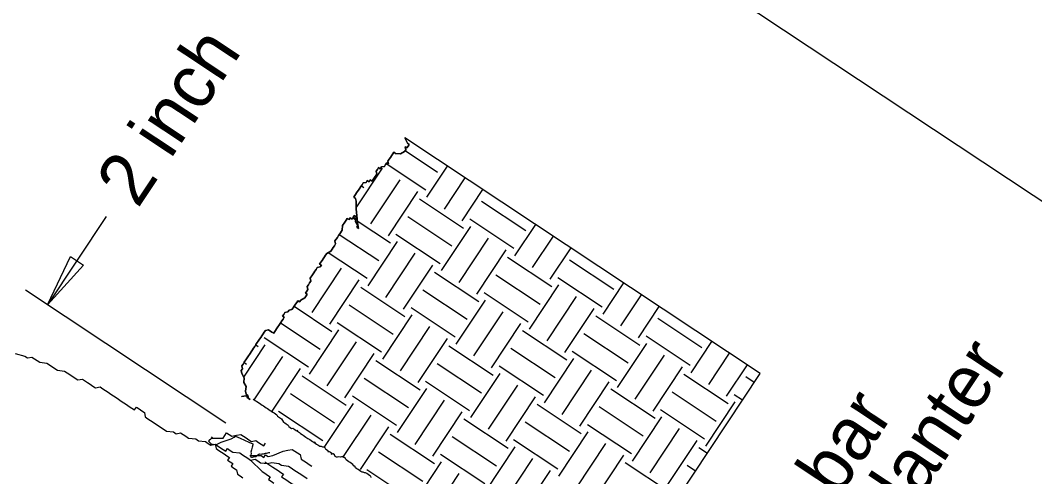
# Model space of a CAD drawing. Extents: x 561231 to 564240, y 590260 to 602519.
# Drawn here: x 563580.5 to 563651.6, y 590919.7 to 590951.7 of the extents above; entities that cross this region are included whole.
import ezdxf

# ---------------------------------------------------------------- set-up
doc = ezdxf.new("R2010")
doc.units = 0
doc.layers.add('Old_Level_1', color=7, linetype='Continuous')

msp = doc.modelspace()

# ---------------------------------------------------------------- linework, layer by layer
at = {"layer": 'Old_Level_1'}
for p, q in [((563974.316, 590725.26), (563449.318, 591073.509)), ((563632.39, 590926.921), (563607.472, 590943.449)), ((563607.495, 590942.538), (563609.769, 590941.03)), ((563606.175, 590941.628), (563608.947, 590939.79)), ((563604.064, 590938.534), (563605.914, 590941.322)), ((563609.015, 590939.266), (563610.47, 590941.461)), ((563605.098, 590937.399), (563607.154, 590940.5)), ((563610.255, 590938.444), (563611.71, 590940.638)), ((563604.427, 590940.077), (563604.597, 590939.963)), ((563606.338, 590936.577), (563608.395, 590939.677)), ((563611.495, 590937.621), (563612.95, 590939.815)), ((563608.499, 590939.161), (563611.599, 590937.105)), ((563612.848, 590938.988), (563615.949, 590936.931)), ((563586.548, 590937.919), (563582.435, 590931.718)), ((563603.831, 590937.825), (563604.039, 590937.688)), ((563604.139, 590937.622), (563606.479, 590936.069)), ((563607.676, 590937.921), (563610.777, 590935.865)), ((563612.025, 590937.747), (563615.126, 590935.691)), ((563615.194, 590935.167), (563616.65, 590937.362)), ((563602.884, 590936.668), (563605.656, 590934.829)), ((563606.854, 590936.681), (563609.954, 590934.625)), ((563610.036, 590934.124), (563612.093, 590937.224)), ((563616.434, 590934.344), (563617.889, 590936.539)), ((563604.902, 590933.065), (563606.958, 590936.165)), ((563611.277, 590933.301), (563613.333, 590936.401)), ((563602.108, 590935.397), (563604.834, 590933.589)), ((563606.142, 590932.242), (563608.198, 590935.343)), ((563612.517, 590932.478), (563614.573, 590935.579)), ((563617.674, 590933.522), (563619.129, 590935.717)), ((563607.382, 590931.42), (563609.439, 590934.52)), ((563614.678, 590935.063), (563617.779, 590933.006)), ((563619.027, 590934.889), (563622.128, 590932.833)), ((563600.984, 590931.199), (563603.041, 590934.299)), ((563609.558, 590934.027), (563612.658, 590931.971)), ((563613.855, 590933.822), (563616.956, 590931.766)), ((563602.225, 590930.376), (563604.281, 590933.477)), ((563616.216, 590930.024), (563618.272, 590933.125)), ((563618.205, 590933.649), (563621.305, 590931.592)), ((563621.373, 590931.068), (563622.828, 590933.263)), ((563594.917, 590923.438), (563580.885, 590932.746)), ((563604.386, 590932.961), (563607.486, 590930.904)), ((563608.735, 590932.787), (563611.835, 590930.731)), ((563613.033, 590932.583), (563616.133, 590930.526)), ((563617.456, 590929.202), (563619.512, 590932.303)), ((563622.613, 590930.246), (563624.069, 590932.44)), ((563599.718, 590931.625), (563602.366, 590929.869)), ((563603.563, 590931.721), (563606.664, 590929.664)), ((563611.081, 590928.966), (563613.137, 590932.067)), ((563623.853, 590929.423), (563625.309, 590931.618)), ((563605.923, 590927.922), (563607.98, 590931.023)), ((563607.912, 590931.547), (563611.013, 590929.49)), ((563612.321, 590928.144), (563614.377, 590931.244)), ((563618.696, 590928.379), (563620.752, 590931.48)), ((563620.857, 590930.964), (563623.957, 590928.907)), ((563598.771, 590930.467), (563601.543, 590928.628)), ((563602.741, 590930.48), (563605.841, 590928.424)), ((563607.164, 590927.1), (563609.22, 590930.2)), ((563613.561, 590927.321), (563615.618, 590930.422)), ((563625.206, 590930.79), (563628.307, 590928.734)), ((563597.62, 590929.445), (563600.721, 590927.388)), ((563600.788, 590926.864), (563602.845, 590929.965)), ((563615.737, 590929.928), (563618.837, 590927.872)), ((563620.035, 590929.724), (563623.135, 590927.667)), ((563624.384, 590929.55), (563627.484, 590927.494)), ((563596.192, 590926.666), (563597.688, 590928.921)), ((563597.024, 590928.915), (563597.194, 590928.802)), ((563602.028, 590926.042), (563604.085, 590929.142)), ((563608.404, 590926.277), (563610.46, 590929.378)), ((563610.565, 590928.862), (563613.665, 590926.805)), ((563622.395, 590925.926), (563624.452, 590929.026)), ((563627.552, 590926.97), (563629.007, 590929.164)), ((563596.914, 590925.062), (563598.928, 590928.098)), ((563603.268, 590925.219), (563605.325, 590928.319)), ((563614.914, 590928.688), (563618.015, 590926.632)), ((563619.212, 590928.484), (563622.312, 590926.427)), ((563623.635, 590925.103), (563625.692, 590928.203)), ((563628.792, 590926.147), (563630.247, 590928.341)), ((563596.201, 590927.675), (563596.371, 590927.562)), ((563605.445, 590927.826), (563608.545, 590925.77)), ((563609.742, 590927.622), (563612.842, 590925.565)), ((563614.092, 590927.448), (563617.192, 590925.392)), ((563617.26, 590924.868), (563619.316, 590927.968)), ((563624.875, 590924.281), (563626.932, 590927.381)), ((563630.032, 590925.324), (563631.488, 590927.519)), ((563598.13, 590924.202), (563600.168, 590927.275)), ((563600.273, 590926.76), (563603.373, 590924.703)), ((563604.622, 590926.586), (563607.722, 590924.53)), ((563607.942, 590890.064), (563632.39, 590926.921)), ((563612.102, 590923.824), (563614.159, 590926.924)), ((563618.5, 590924.045), (563620.556, 590927.145)), ((563627.036, 590926.865), (563630.136, 590924.809)), ((563631.385, 590926.692), (563631.978, 590926.299)), ((563608.92, 590926.382), (563612.02, 590924.325)), ((563613.343, 590923.001), (563615.399, 590926.101)), ((563619.74, 590923.222), (563621.797, 590926.323)), ((563599.45, 590925.52), (563602.55, 590923.463)), ((563603.799, 590925.346), (563606.9, 590923.289)), ((563606.967, 590922.766), (563609.024, 590925.866)), ((563614.583, 590922.179), (563616.639, 590925.279)), ((563621.916, 590925.83), (563625.016, 590923.773)), ((563626.214, 590925.625), (563629.314, 590923.569)), ((563630.563, 590925.451), (563631.155, 590925.059)), ((563601.81, 590921.722), (563603.867, 590924.822)), ((563608.207, 590921.943), (563610.264, 590925.044)), ((563616.744, 590924.763), (563619.844, 590922.707)), ((563621.093, 590924.59), (563624.194, 590922.533)), ((563628.574, 590921.827), (563630.631, 590924.927)), ((563598.627, 590924.28), (563601.727, 590922.223)), ((563603.128, 590921.016), (563605.107, 590923.999)), ((563609.447, 590921.12), (563611.504, 590924.221)), ((563623.438, 590920.769), (563625.495, 590923.869)), ((563625.391, 590924.385), (563628.491, 590922.328)), ((563604.368, 590920.194), (563606.347, 590923.177)), ((563611.623, 590923.728), (563614.724, 590921.671)), ((563615.921, 590923.523), (563619.021, 590921.467)), ((563620.271, 590923.349), (563623.371, 590921.293)), ((563624.679, 590919.946), (563626.735, 590923.047)), ((563599.952, 590922.912), (563599.972, 590922.942)), ((563606.452, 590922.661), (563609.552, 590920.605)), ((563610.801, 590922.487), (563613.901, 590920.431)), ((563618.281, 590919.725), (563620.338, 590922.825)), ((563601.168, 590922.052), (563601.212, 590922.119)), ((563613.146, 590918.667), (563615.203, 590921.767)), ((563615.099, 590922.283), (563618.199, 590920.226)), ((563619.522, 590918.903), (563621.578, 590922.003)), ((563625.919, 590919.124), (563627.975, 590922.224)), ((563628.095, 590921.731), (563628.687, 590921.338)), ((563605.629, 590921.421), (563608.729, 590919.365)), ((563609.978, 590921.247), (563613.079, 590919.191)), ((563614.386, 590917.844), (563616.443, 590920.945)), ((563620.762, 590918.08), (563622.818, 590921.18)), ((563604.806, 590920.181), (563607.907, 590918.124)), ((563607.99, 590917.623), (563610.046, 590920.723)), ((563622.923, 590920.664), (563626.023, 590918.608)), ((563627.272, 590920.491), (563627.864, 590920.098)), ((563609.23, 590916.801), (563611.286, 590919.901)), ((563615.627, 590917.022), (563617.683, 590920.122))]:
    msp.add_line(p, q, dxfattribs=at)
for points in [[(563603.115, 590937.286), (563603.28, 590937.535), (563603.362, 590937.659), (563603.445, 590937.784), (563603.57, 590937.701), (563603.652, 590937.826), (563603.776, 590937.743), (563603.652, 590937.826), (563603.776, 590937.743), (563603.859, 590937.868), (563603.984, 590937.785), (563603.859, 590937.868), (563603.942, 590937.992), (563604.067, 590937.909), (563604.026, 590937.578), (563604.192, 590937.288), (563604.11, 590937.164), (563604.234, 590937.081), (563604.15, 590937.495), (563604.065, 590938.448), (563604.064, 590938.988), (563604.022, 590939.195), (563603.897, 590939.277), (563603.979, 590939.402), (563604.144, 590939.651), (563604.227, 590939.775), (563604.31, 590939.9), (563604.392, 590940.024), (563604.475, 590940.149), (563604.558, 590940.273), (563604.765, 590940.315), (563604.847, 590940.439), (563604.972, 590940.357), (563605.055, 590940.482), (563605.18, 590940.399), (563605.262, 590940.523), (563605.345, 590940.648), (563605.51, 590940.897), (563605.468, 590941.104), (563605.55, 590941.228), (563605.633, 590941.353), (563605.757, 590941.27), (563605.84, 590941.395), (563606.047, 590941.436), (563606.13, 590941.561), (563606.213, 590941.686), (563606.337, 590941.603), (563606.295, 590941.81), (563606.378, 590941.935), (563606.46, 590942.059), (563606.543, 590942.184), (563606.625, 590942.308), (563606.708, 590942.433), (563606.833, 590942.35), (563607.164, 590942.31), (563607.454, 590942.476), (563607.537, 590942.6), (563607.494, 590942.808), (563607.619, 590942.725), (563607.702, 590942.85), (563607.785, 590942.974), (563607.659, 590943.057), (563607.472, 590943.449), (563607.472, 590943.449)], [(563607.472, 590943.449), (563607.472, 590943.449), (563607.659, 590943.057), (563607.785, 590942.974), (563607.702, 590942.85), (563607.619, 590942.725), (563607.494, 590942.808), (563607.537, 590942.6), (563607.454, 590942.476), (563607.164, 590942.31), (563606.833, 590942.35), (563606.708, 590942.433), (563606.625, 590942.308), (563606.543, 590942.184), (563606.46, 590942.059), (563606.378, 590941.935), (563606.295, 590941.81), (563606.337, 590941.603), (563606.213, 590941.686), (563606.13, 590941.561), (563606.047, 590941.436), (563605.84, 590941.395), (563605.757, 590941.27), (563605.633, 590941.353), (563605.55, 590941.228), (563605.468, 590941.104), (563605.51, 590940.897), (563605.345, 590940.648), (563605.262, 590940.523), (563605.18, 590940.399), (563605.055, 590940.482), (563604.972, 590940.357), (563604.847, 590940.439), (563604.765, 590940.315), (563604.558, 590940.273), (563604.475, 590940.149), (563604.392, 590940.024), (563604.31, 590939.9), (563604.227, 590939.775), (563604.144, 590939.651), (563603.979, 590939.402), (563603.897, 590939.277), (563604.022, 590939.195), (563604.064, 590938.988), (563604.065, 590938.448), (563604.15, 590937.495), (563604.234, 590937.081), (563604.11, 590937.164), (563604.192, 590937.288), (563604.026, 590937.578), (563604.067, 590937.909), (563603.942, 590937.992), (563603.859, 590937.868), (563603.984, 590937.785), (563603.859, 590937.868), (563603.776, 590937.743), (563603.652, 590937.826), (563603.776, 590937.743), (563603.652, 590937.826), (563603.57, 590937.701), (563603.445, 590937.784), (563603.362, 590937.659), (563603.28, 590937.535), (563603.115, 590937.286)], [(563596.018, 590925.285), (563596.056, 590925.293), (563596.47, 590925.376), (563596.388, 590925.252), (563596.512, 590925.169), (563596.637, 590925.087), (563596.512, 590925.169), (563596.47, 590925.376), (563596.346, 590925.459), (563596.303, 590925.666), (563596.344, 590925.998), (563596.178, 590926.288), (563596.219, 590926.619), (563596.051, 590926.909), (563596.01, 590927.116), (563596.093, 590927.241), (563596.05, 590927.448), (563596.133, 590927.573), (563596.215, 590927.697), (563596.381, 590927.946), (563596.463, 590928.071), (563596.629, 590928.32), (563596.711, 590928.444), (563596.793, 590928.569), (563596.876, 590928.693), (563596.959, 590928.818), (563597.041, 590928.942), (563597.289, 590929.316), (563597.371, 590929.44), (563597.454, 590929.565), (563597.537, 590929.69), (563597.62, 590929.814), (563597.702, 590929.938), (563597.909, 590929.98), (563598.159, 590929.814), (563598.283, 590929.732), (563598.366, 590929.856), (563598.531, 590930.106), (563598.696, 590930.355), (563598.779, 590930.479), (563598.862, 590930.604), (563598.944, 590930.728), (563599.027, 590930.853), (563598.902, 590930.936), (563598.985, 590931.06), (563599.068, 590931.185), (563599.275, 590931.227), (563599.357, 590931.351), (563599.564, 590931.393), (563599.647, 590931.517), (563599.729, 590931.642), (563599.812, 590931.767), (563599.894, 590931.891), (563599.977, 590932.016), (563600.102, 590931.932), (563600.185, 590932.057), (563600.474, 590932.224), (563600.556, 590932.348), (563600.639, 590932.472), (563600.515, 590932.555), (563600.598, 590932.68), (563600.68, 590932.804), (563600.638, 590933.012), (563600.721, 590933.136), (563600.803, 590933.26), (563600.886, 590933.385), (563600.844, 590933.592), (563601.009, 590933.841), (563601.092, 590933.966), (563601.174, 590934.09), (563601.257, 590934.215), (563601.339, 590934.339), (563601.546, 590934.381), (563601.629, 590934.506), (563601.504, 590934.588), (563601.588, 590934.713), (563601.67, 590934.837), (563601.752, 590934.962), (563601.835, 590935.086), (563601.918, 590935.211), (563602, 590935.336), (563602.29, 590935.502), (563602.372, 590935.626), (563602.455, 590935.751), (563602.538, 590935.876), (563602.62, 590936), (563602.578, 590936.207), (563602.661, 590936.332), (563602.744, 590936.457), (563602.826, 590936.58), (563602.909, 590936.705), (563603.074, 590936.954), (563603.115, 590937.286)], [(563603.115, 590937.286), (563603.074, 590936.954), (563602.909, 590936.705), (563602.826, 590936.58), (563602.744, 590936.457), (563602.661, 590936.332), (563602.578, 590936.207), (563602.62, 590936), (563602.538, 590935.876), (563602.455, 590935.751), (563602.372, 590935.626), (563602.29, 590935.502), (563602, 590935.336), (563601.918, 590935.211), (563601.835, 590935.086), (563601.752, 590934.962), (563601.67, 590934.837), (563601.588, 590934.713), (563601.504, 590934.588), (563601.629, 590934.506), (563601.546, 590934.381), (563601.339, 590934.339), (563601.257, 590934.215), (563601.174, 590934.09), (563601.092, 590933.966), (563601.009, 590933.841), (563600.844, 590933.592), (563600.886, 590933.385), (563600.803, 590933.26), (563600.721, 590933.136), (563600.638, 590933.012), (563600.68, 590932.804), (563600.598, 590932.68), (563600.515, 590932.555), (563600.639, 590932.472), (563600.556, 590932.348), (563600.474, 590932.224), (563600.185, 590932.057), (563600.102, 590931.932), (563599.977, 590932.016), (563599.894, 590931.891), (563599.812, 590931.767), (563599.729, 590931.642), (563599.647, 590931.517), (563599.564, 590931.393), (563599.357, 590931.351), (563599.275, 590931.227), (563599.068, 590931.185), (563598.985, 590931.06), (563598.902, 590930.936), (563599.027, 590930.853), (563598.944, 590930.728), (563598.862, 590930.604), (563598.779, 590930.479), (563598.696, 590930.355), (563598.531, 590930.106), (563598.366, 590929.856), (563598.283, 590929.732), (563598.159, 590929.814), (563597.909, 590929.98), (563597.702, 590929.938), (563597.62, 590929.814), (563597.537, 590929.69), (563597.454, 590929.565), (563597.371, 590929.44), (563597.289, 590929.316), (563597.041, 590928.942), (563596.959, 590928.818), (563596.876, 590928.693), (563596.793, 590928.569), (563596.711, 590928.444), (563596.629, 590928.32), (563596.463, 590928.071), (563596.381, 590927.946), (563596.215, 590927.697), (563596.133, 590927.573), (563596.05, 590927.448), (563596.093, 590927.241), (563596.01, 590927.116), (563596.051, 590926.909), (563596.219, 590926.619), (563596.178, 590926.288), (563596.344, 590925.998), (563596.303, 590925.666), (563596.346, 590925.459), (563596.47, 590925.376), (563596.512, 590925.169), (563596.637, 590925.087), (563596.512, 590925.169), (563596.388, 590925.252), (563596.47, 590925.376), (563596.056, 590925.293), (563596.018, 590925.285)], [(563580.149, 590928.314), (563580.832, 590928.13), (563581.018, 590928.006), (563581.327, 590928.068), (563581.7, 590927.821), (563581.887, 590927.697), (563582.383, 590927.636), (563582.569, 590927.513), (563582.942, 590927.266), (563583.129, 590927.141), (563583.624, 590927.081), (563583.998, 590926.834), (563584.37, 590926.586), (563584.557, 590926.463), (563584.867, 590926.525), (563585.239, 590926.279), (563585.426, 590926.155), (563585.612, 590926.031), (563585.799, 590925.907), (563586.108, 590925.97), (563586.295, 590925.846), (563586.481, 590925.723), (563586.668, 590925.599), (563586.854, 590925.475), (563587.04, 590925.352), (563587.227, 590925.228), (563587.413, 590925.105), (563587.6, 590924.981), (563587.786, 590924.857), (563587.972, 590924.734), (563588.158, 590924.61), (563588.345, 590924.487), (563588.531, 590924.363), (563588.655, 590924.549), (563588.841, 590924.426), (563589.027, 590924.302), (563589.214, 590924.178), (563589.276, 590923.868), (563589.463, 590923.744), (563589.649, 590923.621), (563589.835, 590923.498), (563590.208, 590923.25), (563590.395, 590923.127), (563590.768, 590922.879), (563591.264, 590922.819), (563591.451, 590922.695), (563591.76, 590922.757), (563592.133, 590922.51), (563592.319, 590922.387), (563592.816, 590922.325), (563593.002, 590922.202), (563593.499, 590922.141), (563593.684, 590922.017), (563593.871, 590921.894), (563594.181, 590921.956), (563594.554, 590921.709), (563594.74, 590921.585), (563594.926, 590921.462), (563595.049, 590921.648), (563595.236, 590921.524), (563595.423, 590921.401), (563595.919, 590921.34), (563596.105, 590921.216), (563596.292, 590921.092), (563596.478, 590920.969), (563596.665, 590920.845), (563596.974, 590920.908), (563597.161, 590920.784), (563597.347, 590920.661), (563597.844, 590920.599), (563598.153, 590920.662), (563598.65, 590920.601), (563598.836, 590920.478), (563599.332, 590920.416), (563599.519, 590920.293), (563599.705, 590920.169), (563599.892, 590920.045), (563600.078, 590919.922), (563600.264, 590919.798), (563600.637, 590919.551)], [(563596.853, 590925.111), (563597.284, 590924.825), (563597.378, 590924.763), (563597.471, 590924.702), (563597.564, 590924.64), (563597.657, 590924.578), (563597.75, 590924.516), (563597.844, 590924.455), (563597.937, 590924.393), (563598.031, 590924.331), (563598.123, 590924.269), (563598.216, 590924.207), (563598.309, 590924.145), (563598.403, 590924.084), (563598.496, 590924.022), (563598.558, 590923.914), (563598.698, 590923.821), (563598.838, 590923.728), (563598.9, 590923.619), (563598.962, 590923.511), (563599.055, 590923.449), (563599.148, 590923.388), (563599.288, 590923.295), (563599.351, 590923.187), (563599.444, 590923.124), (563599.537, 590923.062), (563599.615, 590923.078), (563599.754, 590922.985), (563599.847, 590922.924), (563599.941, 590922.862), (563600.081, 590922.769), (563600.173, 590922.707), (563600.267, 590922.645), (563600.36, 590922.584), (563600.453, 590922.522), (563600.547, 590922.46), (563600.686, 590922.367), (563600.825, 590922.275), (563600.919, 590922.213), (563601.012, 590922.151), (563601.106, 590922.089), (563601.198, 590922.027), (563601.292, 590921.965), (563601.385, 590921.904), (563601.525, 590921.811), (563601.602, 590921.827), (563601.695, 590921.765), (563601.773, 590921.781), (563601.867, 590921.719), (563601.882, 590921.642), (563601.975, 590921.579), (563602.069, 590921.518), (563602.084, 590921.44), (563602.162, 590921.456), (563602.255, 590921.394), (563602.348, 590921.332), (563602.363, 590921.255), (563602.363, 590921.255), (563602.348, 590921.332)], [(563593.931, 590922.39), (563593.972, 590922.462), (563593.91, 590922.369), (563593.849, 590922.276), (563593.772, 590922.26), (563593.71, 590922.167), (563593.71, 590922.167), (563593.865, 590921.997), (563593.959, 590921.935), (563594.036, 590921.951), (563594.16, 590921.936), (563594.315, 590921.967), (563594.609, 590922.107), (563594.872, 590922.201), (563595.291, 590922.325), (563595.507, 590922.45), (563595.616, 590922.512), (563595.927, 590922.373), (563596.237, 590922.234), (563596.547, 590922.095), (563596.811, 590921.988), (563596.826, 590921.91), (563596.781, 590921.739), (563596.735, 590921.569), (563596.688, 590921.398), (563596.705, 590921.32), (563596.689, 590921.196), (563596.627, 590921.103), (563596.72, 590921.042), (563596.798, 590921.057), (563596.875, 590921.073), (563597.03, 590921.104), (563597.17, 590921.213), (563597.278, 590921.276), (563597.403, 590921.26), (563597.48, 590921.276), (563597.557, 590921.292), (563597.635, 590921.307), (563597.712, 590921.323), (563597.789, 590921.338), (563597.867, 590921.354), (563597.944, 590921.369), (563598.022, 590921.385)], [(563593.931, 590922.39), (563594.738, 590922.391), (563594.862, 590922.578), (563594.985, 590922.764), (563595.171, 590922.64), (563595.358, 590922.516), (563595.668, 590922.579), (563595.977, 590922.642), (563596.164, 590922.518), (563596.35, 590922.395), (563596.537, 590922.271), (563596.723, 590922.147), (563597.033, 590922.21), (563597.22, 590922.086), (563597.406, 590921.963), (563597.592, 590921.84), (563597.716, 590922.026)], [(563594.181, 590921.956), (563594.244, 590921.646), (563594.43, 590921.522), (563594.617, 590921.399), (563594.803, 590921.276), (563594.989, 590921.152), (563595.176, 590921.028), (563595.052, 590920.842), (563595.238, 590920.719), (563595.425, 590920.595), (563595.301, 590920.408), (563595.487, 590920.285), (563595.674, 590920.161), (563595.737, 590919.851), (563595.924, 590919.728), (563596.11, 590919.604)], [(563596.602, 590921.155), (563597.408, 590921.156), (563597.594, 590921.033), (563597.718, 590921.219), (563597.904, 590921.096), (563598.214, 590921.158), (563598.958, 590921.47), (563599.267, 590921.533), (563599.578, 590921.595), (563599.764, 590921.472), (563599.951, 590921.348), (563600.137, 590921.224), (563600.199, 590920.915), (563600.386, 590920.791), (563600.572, 590920.667), (563600.758, 590920.544), (563600.945, 590920.42)], [(563602.596, 590921.101), (563602.534, 590921.209), (563602.441, 590921.27), (563602.363, 590921.255), (563602.286, 590921.239)], [(563602.845, 590921.07), (563602.767, 590921.054), (563602.69, 590921.038), (563602.596, 590921.101)], [(563605.112, 590919.633), (563605.096, 590919.71), (563605.003, 590919.772), (563604.91, 590919.834), (563604.817, 590919.896), (563604.724, 590919.957), (563604.647, 590919.942), (563604.553, 590920.004), (563604.475, 590919.988), (563604.382, 590920.05), (563604.289, 590920.112), (563604.196, 590920.174), (563604.103, 590920.235), (563604.01, 590920.297), (563603.994, 590920.375), (563603.9, 590920.436), (563603.838, 590920.545), (563603.745, 590920.607), (563603.652, 590920.669), (563603.559, 590920.73), (563603.465, 590920.792), (563603.372, 590920.854), (563603.31, 590920.963), (563603.217, 590921.024), (563603.124, 590921.086), (563603.046, 590921.07), (563602.969, 590921.055), (563602.845, 590921.07)], [(563596.665, 590920.845), (563597.473, 590920.04), (563597.659, 590919.917), (563597.846, 590919.793), (563598.032, 590919.67), (563597.909, 590919.484), (563598.095, 590919.36), (563598.281, 590919.236)], [(563597.657, 590920.723), (563598.216, 590920.352), (563598.403, 590920.229), (563598.589, 590920.105), (563598.775, 590919.982), (563598.962, 590919.858), (563598.838, 590919.671), (563599.025, 590919.548), (563599.211, 590919.424), (563599.397, 590919.301), (563599.583, 590919.177), (563599.77, 590919.054), (563599.956, 590918.93), (563600.143, 590918.806), (563600.453, 590918.869), (563600.64, 590918.745)]]:
    msp.add_lwpolyline(points, dxfattribs=at)
msp.add_lwpolyline([(563584.957, 590934.51), (563582.435, 590931.718), (563584.026, 590935.127)], close=True, dxfattribs=at)

# ---------------------------------------------------------------- texts
for s, height, p in [('2 inch', 3.7205, (563588.75, 590938.423)), (' 2 inches toward planter', 3.72047, (563620.726, 590883.674)), ('3. Insert planting bar', 3.72047, (563616.74, 590886.318))]:
    msp.add_text(s, height=height, rotation=56.44242, dxfattribs=at).set_placement(p)

doc.saveas('drawing.dxf')
